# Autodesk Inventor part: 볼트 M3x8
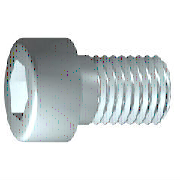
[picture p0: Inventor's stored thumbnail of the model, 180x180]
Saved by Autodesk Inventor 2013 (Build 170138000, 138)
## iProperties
IsCustomPart: 0
Created: 2012-02
Part Number: 볼트 M3x8
Material: 강철, 연강
Description: 6각머리 태핑 나사
Document SubType Name: Modeling
Standard: KS B 1003
Designer: mduedu
Standards Organization: KS
Language: ko-KR
Size Designation: M 3 x 8
Categories: <MemberInstance><Categories><Category DisplayName="조임쇠" InternalName="e4da775c-781d-43d5-af7c-5136215cf5a6" Mnemonic="FSTN"><Category DisplayName="볼트" InternalN
Density: 7.86 g/cm^3
Mass: 0.929843 g
Surface Area: 1.83001 cm^2
Volume: 0.118301 cm^3
Author: mduedu
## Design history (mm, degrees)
sketch "스케치1"
  geometry: L1 (-0.867, 0)-(8, 0); L2 (8, 0)-(8, 1.5); L3 (8, 1.5)-(1.25, 1.5); L4 (1.25, 1.5)-(0.943, 1.5); L5 (0.943, 1.5)-(0, 1.5); L6 (0, 1.5)-(0, 2.75); L7 (0, 2.75)-(-3, 2.75); L8 (-3, 2.75)-(-3, 1.443); L9 (-3, 1.443)-(-1.7, 1.443); L10 (-1.7, 1.443)-(-0.867, 0); L11 (-5.2, 0)-(10.2, 0) reference; L12 (0, -0.55)-(0, 3.3) reference; L13 (1.25, 1.5)-(0, 1.5)
  constraints: 22 end point, 6 parallel, 2 collinear, 2 perpendicular, 1 horizontal, 1 point on line
  dimensions: "d1" = 6.75 distance from line of L3.end L2 (= GEL); "d2" = 0.30683 distance of L4.end L3.end (computed from GAL); "d3" = 3 distance between parallel lines of L8 L6 (= KOH); "d4" = 1.3 distance of L8.end L9.end (= INTI); "d5" = 60 deg angle of L10 L1; "d6" = 3 diameter of L3 L1 (= GD); "d7" = 3 diameter of L5 L1 (= BDM); "d8" = 2.88675 diameter of L9 L1 (= 1.1547 x SW); "d9" = 5.5 diameter of L7 L1 (= KOD); "d26" = 8 distance between parallel lines of L12 L2 (= NLG)
revolve "본체" sketch "스케치1" stored, may be unused: angle "d10" = 90 deg
sketch "스케치2"
  geometry: L1 (0, -3.85)-(0, 3.85) reference; L2 (-3.85, 0)-(3.85, 0) reference; L3 (1.443, 0)-(0.722, -1.25); L4 (0.722, -1.25)-(-0.722, -1.25); L5 (-0.722, -1.25)-(-1.443, 0); L6 (-1.443, 0)-(-0.722, 1.25); L7 (-0.722, 1.25)-(0.722, 1.25); L8 (0.722, 1.25)-(1.443, 0); 2 further points
  constraints: 12 end point, 1 coincident, 1 horizontal alignment, 1 point on line, 12 other
extrude "슬롯" join sketch "스케치2" stored distance "d11" = 10; taper "d12" = 0 deg
workplane "Work Plane1"
fillet "Fillet2" dims "d30" = 0.1 (= R)
body "Solid1"
fillet "모깎기1" dims "d17" = 0.3 (= RR)
feature "스레드" dims "d13" = 6.75 (= GEL), "d14" = 0
chamfer "모따기1" distance "d15" = 0.30673 (= -0.5 x SPD + 0.5 x GD); stored, may be unused: second distance "d16" = 0.30673 (= GUL), angle "d27" = 45 deg
other parameters: "GD" = 3 (= NND) [user parameter; used in 2 equation terms], "NLG" = 8 [user parameter; used in 1 equation term], "GEL" = 6.75 [user parameter; used in 2 equation terms], "KOD" = 5.5 [user parameter; used in 1 equation term], "KOH" = 3 [user parameter; used in 1 equation term], "INTI" = 1.3 [user parameter; used in 1 equation term], "GAL" = 0.30673 (= 0.61345 x PTC) [user parameter; used in 1 equation term], "GUL" = 0.30673 (= 0.61345 x PTC) [user parameter; used in 1 equation term], "BDM" = 3 (= NND) [user parameter; used in 1 equation term], "SW" = 2.5 [user parameter; used in 2 equation terms], "RR" = 0.3 [user parameter; used in 1 equation term], "SPD" = 2.38655 (= NND - 1.2269 x PTC) [user parameter; used in 1 equation term], "d19" = 0, "d28" = 0, "d29" = 0, "R" = 0.1 [user parameter; used in 1 equation term], "PHH" = 0.1 [user parameter], "GD1" = 2.38655 (= THREADDIA - 1.2269 x PTC) [user parameter], "THREADDIA" = 3 [user parameter; used in 1 equation term], "FAWI" = 45 deg [user parameter], "PTC" = 0.5 [user parameter; used in 5 equation terms], "NND" = 3 [user parameter; used in 3 equation terms], "TOA" = 30 deg [user parameter], "E0" = 2.8875 (= 1.155 x SW) [user parameter]
